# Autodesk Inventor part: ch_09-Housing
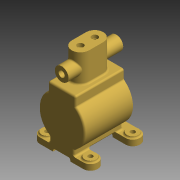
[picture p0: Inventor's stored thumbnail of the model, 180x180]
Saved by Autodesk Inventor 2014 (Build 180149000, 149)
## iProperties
Shininess: 0.0
Length Units: 11268
Angle Units: 11279
Time Units: 11290
Mass Units: 11283
Length Display Precision: 3
Angle Display Precision: 1
Compacted: True
Created: 1999-06
Part Number: ch_09-Housing
Material: Rubiconium
Document SubType Name: Modeling
Designer: Administrator
Density: 1 g/cm^3
Appearance: Rubigold
Density: 0.0
Volumn: 0.0
Area: 0.0
PropertySet Name: Model Information
Control State: 0
Master: False
Checked Out: False
Author: Administrator
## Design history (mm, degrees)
body "Solid1"
  node "Base1"
  node "y-z Plane"
  node "x-z Plane"
  node "x-y Plane"
